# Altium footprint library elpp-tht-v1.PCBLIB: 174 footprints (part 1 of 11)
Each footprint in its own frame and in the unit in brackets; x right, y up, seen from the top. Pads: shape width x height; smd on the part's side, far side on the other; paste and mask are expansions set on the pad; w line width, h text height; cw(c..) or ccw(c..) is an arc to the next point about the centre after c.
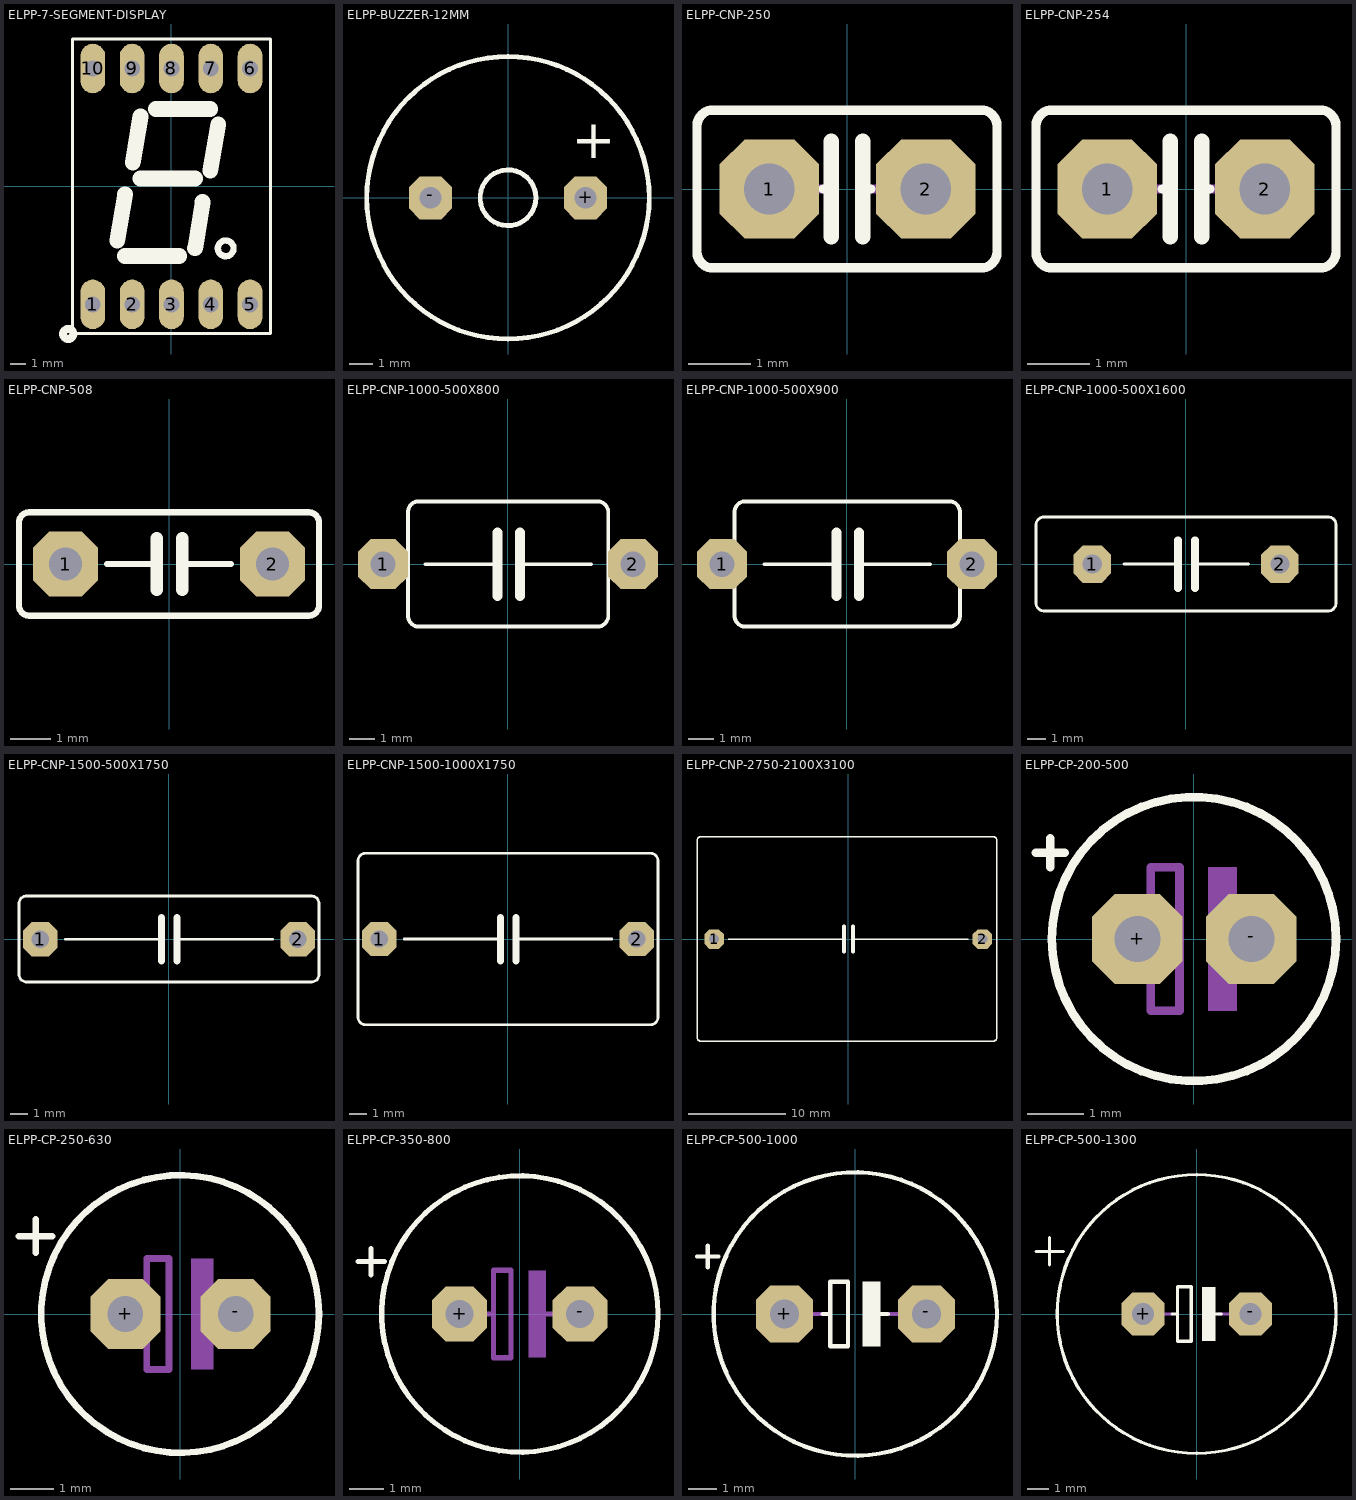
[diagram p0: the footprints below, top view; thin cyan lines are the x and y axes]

## ELPP-7-SEGMENT-DISPLAY [mil]
pads (10):
  oval 63x126 hole 40: 1(-200,-300) 2(-100,-300) 3(0,-300) 4(100,-300) 5(200,-300) 6(200,300) 7(100,300) 8(0,300) 9(-100,300) 10(-200,300)
Top Overlay:
  circle w20: c-262.5,-375 r13
  circle w16: c138,-157.48 r20
  lines w8: -251.97,-374.02 -251.97,375 252,375 252,-374.02 -251.97,-374.02
  lines w40: -137.8,-137.8 -118.11,-19.68 ; -118.11,-177.17 20,-177.17 ; -98.43,60 -78.74,178 ; -78.74,20 60,20 ; -39.37,197 99,197 ; 60,-157.48 79,-39.37 ; 99,40 119,158
Mechanical 2:
  text ">NAME" at -262.5,-325 h42.5
Mechanical 4:
  text ">VALUE" at 313,-200 h42.5

## ELPP-BUZZER-12MM [mil]
pads (2):
  oct 71x71 hole 36: +(128,0) -(-127.95,0)
Top Overlay:
  circle w8: c0,0 r233
  circle w8: c0,0 r46
  text "+" at 105,45 h108.5
Mechanical 2:
  text ">NAME" at 150,200 h42.5
Mechanical 4:
  text ">VALUE" at -125,-120 h42.5

## ELPP-CNP-250 [mil]
pads (2):
  oct 63x63 hole 32: 1(-49.21,0) 2(50,0)
Top Overlay:
  lines w6: -15,0 -10,0 ; 10,0 15,0 ; -95,-40 -95,40 cw(c-85,40) -85,50 85,50 cw(c85,40) 95,40 95,-40 cw(c85,-40) 85,-50 -85,-50 cw(c-85,-40) -95,-40
  lines w10: -10,-30 -10,0 -10,30 ; 10,-30 10,0 10,30
Mechanical 2:
  text ">NAME" at -90,60 h42.5
Mechanical 4:
  text ">VALUE" at -90,-110 h42.5
Mechanical 16:
  lines w6: -30,0 -15,0 ; 15,0 30,0

## ELPP-CNP-254 [mil]
pads (2):
  oct 63x63 hole 32: 1(-50,0) 2(50,0)
Top Overlay:
  lines w6: -15,0 -10,0 ; 10,0 15,0 ; -95,-40 -95,40 cw(c-85,40) -85,50 85,50 cw(c85,40) 95,40 95,-40 cw(c85,-40) 85,-50 -85,-50 cw(c-85,-40) -95,-40
  lines w10: -10,-30 -10,0 -10,30 ; 10,-30 10,0 10,30
Mechanical 2:
  text ">NAME" at -90,60 h42.5
Mechanical 4:
  text ">VALUE" at -90,-110 h42.5
Mechanical 16:
  lines w6: -30,0 -15,0 ; 15,0 30,0

## ELPP-CNP-508 [mil]
pads (2):
  oct 63x63 hole 32: 1(-100,0) 2(100,0)
Top Overlay:
  lines w6: -60,0 -12,0 ; 13,0 60,0 ; -145,-40 -145,40 cw(c-135,40) -135,50 135,50 cw(c135,40) 145,40 145,-40 cw(c135,-40) 135,-50 -135,-50 cw(c-135,-40) -145,-40
  lines w12: -12,-25 -12,0 -12,25 ; 13,-25 13,0 13,25
Mechanical 2:
  text ">NAME" at -135,65 h42.5
Mechanical 4:
  text ">VALUE" at -135,-110 h42.5

## ELPP-CNP-1000-500X800 [mil]
pads (2):
  oct 79x79 hole 40: 1(-196.85,0) 2(197,0)
Top Overlay:
  lines w6: -130.31,0 -16.73,0 ; 19,0 131,0 ; -157.48,-80.31 -157.48,81 cw(c-140.53,82.05) -141.57,99 142,99 cw(c141,82) 158,81 158,-80.31 cw(c140.94,-81.37) 142,-98.43 -141.57,-98.43 cw(c-140.47,-81.42) -157.48,-80.32
  lines w16: -16.73,-50 -16.73,0 -16.73,50 ; 19,-50 19,0 19,50
Mechanical 2:
  text ">NAME" at -161.26,116 h42.5
Mechanical 4:
  text ">VALUE" at -158.43,-168.58 h42.5

## ELPP-CNP-1000-500X900 [mil]
pads (2):
  oct 79x79 hole 40: 1(-196.85,0) 2(197,0)
Top Overlay:
  lines w6: -177.17,-29.53 -177.17,-80.31 ccw(c-160.16,-81.42) -161.26,-98.43 162,-98.43 ccw(c160.94,-81.37) 178,-80.32 178,-29.53 ; -177.17,30 -177.17,81 cw(c-160.21,82.05) -161.26,99 162,99 cw(c161,82) 178,81 178,30 ; -130.31,0 -16.73,0 ; 19,0 131,0
  lines w16: -16.73,-50 -16.73,0 -16.73,50 ; 19,-50 19,0 19,50
Mechanical 2:
  text ">NAME" at -161.26,116 h42.5
Mechanical 4:
  text ">VALUE" at -158.43,-168.58 h42.5

## ELPP-CNP-1000-500X1600 [mil]
pads (2):
  oct 79x79 hole 40: 1(-196.85,0) 2(197,0)
Top Overlay:
  lines w6: -130.31,0 -16.73,0 ; 19,0 131,0 ; -314.96,-80.31 -314.96,-29.53 -314.96,81 cw(c-298.01,82.05) -299.06,99 300,99 cw(c298.5,82.5) 315,81 315,-29.53 315,-80.31 cw(c298.44,-81.87) 300,-98.43 -299.06,-98.43 cw(c-297.95,-81.42) -314.96,-80.32
  lines w16: -16.73,-50 -16.73,0 -16.73,50 ; 19,-50 19,0 19,50
Mechanical 2:
  text ">NAME" at -161.26,116 h42.5
Mechanical 4:
  text ">VALUE" at -158.43,-168.58 h42.5

## ELPP-CNP-1500-500X1750 [mil]
pads (2):
  oct 79x79 hole 40: 1(-295.28,0) 2(296,0)
Top Overlay:
  lines w6: -238.58,0 -16.73,0 ; 19,0 239,0 ; -344.49,-80.31 -344.49,-29.53 -344.49,81 cw(c-327.54,82.05) -328.58,99 329,99 cw(c328,82) 345,81 345,-29.53 345,-80.31 cw(c327.94,-81.37) 329,-98.43 -328.58,-98.43 cw(c-327.48,-81.42) -344.49,-80.32
  lines w16: -16.73,-50 -16.73,0 -16.73,50 ; 19,-50 19,0 19,50
Mechanical 2:
  text ">NAME" at -161.26,116 h42.5
Mechanical 4:
  text ">VALUE" at -158.43,-168.58 h42.5

## ELPP-CNP-1500-1000X1750 [mil]
pads (2):
  oct 79x79 hole 40: 1(-295.28,0) 2(296,0)
Top Overlay:
  lines w6: -238.58,0 -16.73,0 ; 19,0 239,0 ; -344.49,-178.74 -344.49,-29.53 -344.49,179 cw(c-327.54,180.05) -328.58,197 329,197 cw(c328,180) 345,179 345,-29.53 345,-178.74 cw(c327.94,-179.8) 329,-196.85 -328.58,-196.85 cw(c-327.48,-179.84) -344.49,-178.74
  lines w16: -16.73,-50 -16.73,0 -16.73,50 ; 19,-50 19,0 19,50
Mechanical 2:
  text ">NAME" at -161.26,214 h42.5
Mechanical 4:
  text ">VALUE" at -158.43,-267.01 h42.5

## ELPP-CNP-2750-2100X3100 [mil]
pads (2):
  oct 79x79 hole 40: 1(-541.34,0) 2(542,0)
Top Overlay:
  lines w6: -484.65,0 -16.73,0 ; 19,0 485,0 ; -610.24,-395.28 -610.24,-29.53 -610.24,396 cw(c-593.28,397.05) -594.33,414 585,414 cw(c584,397) 601,396 601,-29.53 601,-395.28 cw(c583.94,-396.33) 585,-413.39 -594.33,-413.39 cw(c-593.23,-396.38) -610.24,-395.28
  lines w16: -16.73,-50 -16.73,0 -16.73,50 ; 19,-50 19,0 19,50
Mechanical 2:
  text ">NAME" at -161.26,431 h42.5
Mechanical 4:
  text ">VALUE" at -158.43,-483.54 h42.5

## ELPP-CP-200-500 [mil]
pads (2):
  oct 63x63 hole 32: +(-39.37,0) -(40,0)
Top Overlay:
  circle w6: c0,0 r99
  lines w6: -110,60 -100,60 ; -100,50 -100,60 ; -100,70 -100,60 ; -90,60 -100,60
Mechanical 2:
  text ">NAME" at 100,50 h42.5
Mechanical 4:
  text ">VALUE" at 100,-100 h42.5
Mechanical 16:
  rectangle: 10,-50 30,50
  lines w6: -65,0 -30,0 ; 25,0 65,0 ; -30,0 -30,-50 -10,-50 -10,50 -30,50 -30,0

## ELPP-CP-250-630 [mil]
pads (2):
  oct 63x63 hole 32: +(-49.21,0) -(50,0)
Top Overlay:
  circle w6: c0,0 r125
  lines w6: -145,70 -130,70 ; -130,55 -130,70 ; -130,85 -130,70 ; -115,70 -130,70
Mechanical 2:
  text ">NAME" at 100,100 h42.5
Mechanical 4:
  text ">VALUE" at 100,-100 h42.5
Mechanical 16:
  rectangle: 10,-50 30,50
  lines w6: -65,0 -30,0 ; 25,0 65,0 ; -30,0 -30,-50 -10,-50 -10,50 -30,50 -30,0

## ELPP-CP-350-800 [mil]
pads (2):
  oct 63x63 hole 32: +(-68.9,0) -(69,0)
Top Overlay:
  circle w6: c0,0 r158
  lines w6: -185,60 -155,60 ; -170,45 -170,75
Mechanical 2:
  text ">NAME" at -125,150 h42.5
Mechanical 4:
  text ">VALUE" at -100,-100 h42.5
Mechanical 16:
  rectangle: 10,-50 30,50
  lines w6: -65,0 -30,0 ; 25,0 65,0 ; -30,0 -30,-50 -10,-50 -10,50 -30,50 -30,0

## ELPP-CP-500-1000 [mil]
pads (2):
  oct 79x79 hole 40: +(-98.43,0) -(99,0)
Top Overlay:
  circle w6: c0,0 r197
  rectangle: 10,-45 35,45
  lines w6: -220,80 -190,80 ; -205,65 -205,95 ; -45,0 -35,0 ; 25,0 45,0 ; -35,0 -35,-45 -10,-45 -10,45 -35,45 -35,0
Mechanical 2:
  text ">NAME" at -155,175 h42.5
Mechanical 4:
  text ">VALUE" at -125,-100 h42.5
Mechanical 16:
  lines w6: -65,0 -45,0 ; 45,0 65,0

## ELPP-CP-500-1300 [mil]
pads (2):
  oct 79x79 hole 40: +(-98.43,0) -(99,0)
Top Overlay:
  circle w6: c0,0 r256
  rectangle: 10,-50 35,50
  lines w6: -295,115 -245,115 ; -270,90 -270,140 ; -45,0 -35,0 ; 25,0 45,0 ; -35,0 -35,-50 -10,-50 -10,50 -35,50 -35,0
Mechanical 2:
  text ">NAME" at -200,215 h42.5
Mechanical 4:
  text ">VALUE" at -125,-125 h42.5
Mechanical 16:
  lines w6: -65,0 -45,0 ; 40,0 60,0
